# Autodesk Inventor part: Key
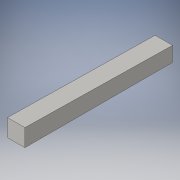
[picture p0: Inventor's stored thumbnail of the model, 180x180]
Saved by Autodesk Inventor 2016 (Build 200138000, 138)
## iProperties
Created: 2020-03
Part Number: Key
Material: Generic
Document SubType Name: Modeling
Designer: Furqan
Density: 1 g/cm^3
Appearance: Default
Author: Furqan
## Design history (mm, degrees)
sketch "Sketch1"
  geometry: L1 (-2.997, -2.997)-(2.997, -2.997); L2 (2.997, -2.997)-(2.997, 2.997); L3 (2.997, 2.997)-(-2.997, 2.997); L4 (-2.997, 2.997)-(-2.997, -2.997); L5 (-2.997, -2.997)-(2.997, 2.997); L6 (2.997, -2.997)-(-2.997, 2.997); 1 further point
  constraints: 12 end point, 2 midpoint, 2 parallel, 1 horizontal, 1 perpendicular
  dimensions: "d0" = 5.9944 distance of L3.end L2.end; "d1" = 5.9944 distance of L2.end L1.end
extrude "Extrusion1" new body sketch "Sketch1" distance "d2" = 50.8; taper "d3" = 0 deg
feature "FaceDraft1" dims angle "d4" = 1 deg
body "Solid1"
